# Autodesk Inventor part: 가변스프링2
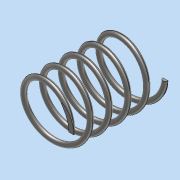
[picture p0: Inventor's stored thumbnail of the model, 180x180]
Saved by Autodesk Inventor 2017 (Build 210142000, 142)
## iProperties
Part Number: 가변스프링2
Material: 강철, 연강
Document SubType Name: Modeling
Designer: MRC
Density: 7.85 g/cm^3
Appearance: 반연마
Mass: 8.42795 g
Surface Area: 21.7305 cm^2
Volume: 1.07362 cm^3
Author: MRC
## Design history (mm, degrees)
sketch "스케치1"
  geometry: L1 (0, 0)-(0, 36.411); L2 (0, 0)-(11, 0); L3 (0, 36.411)-(11, 36.411); C1 r 1 at (11, 0)
  constraints: 6 end point, 2 horizontal, 1 centre point, 1 coincident, 1 vertical
  dimensions: "d0" = 36.4112 distance of L1.start L1.end (derived); "d1" = 11 distance of L1.start L2.end; "d2" = 2 diameter of C1
feature "코일1" pitch "d3" = 10; turns "d5" = 5; dims "d4" = 36.4112 (= d0), "d6" = 0, angle "d7" = 90 deg, angle "d8" = 90 deg, "d9" = 0, "d10" = 0
sketch "스케치2"
  geometry: L1 (36.411, 15)-(0, 15); L2 (0, 15)-(0, -15); L3 (0, -15)-(36.411, -15); L4 (36.411, -15)-(36.411, 15); 2 further points
  constraints: 8 end point, 2 parallel, 1 coincident, 1 horizontal, 1 midpoint, 1 perpendicular
  dimensions: "d11" = 30 distance of L3.end L1.start; "d12" = 36.4112 distance of L2.end L3.end (= d0)
extrude "돌출1" sketch "스케치2" stored distance "d13" = 30; taper "d14" = 0 deg
node "솔리드1"
